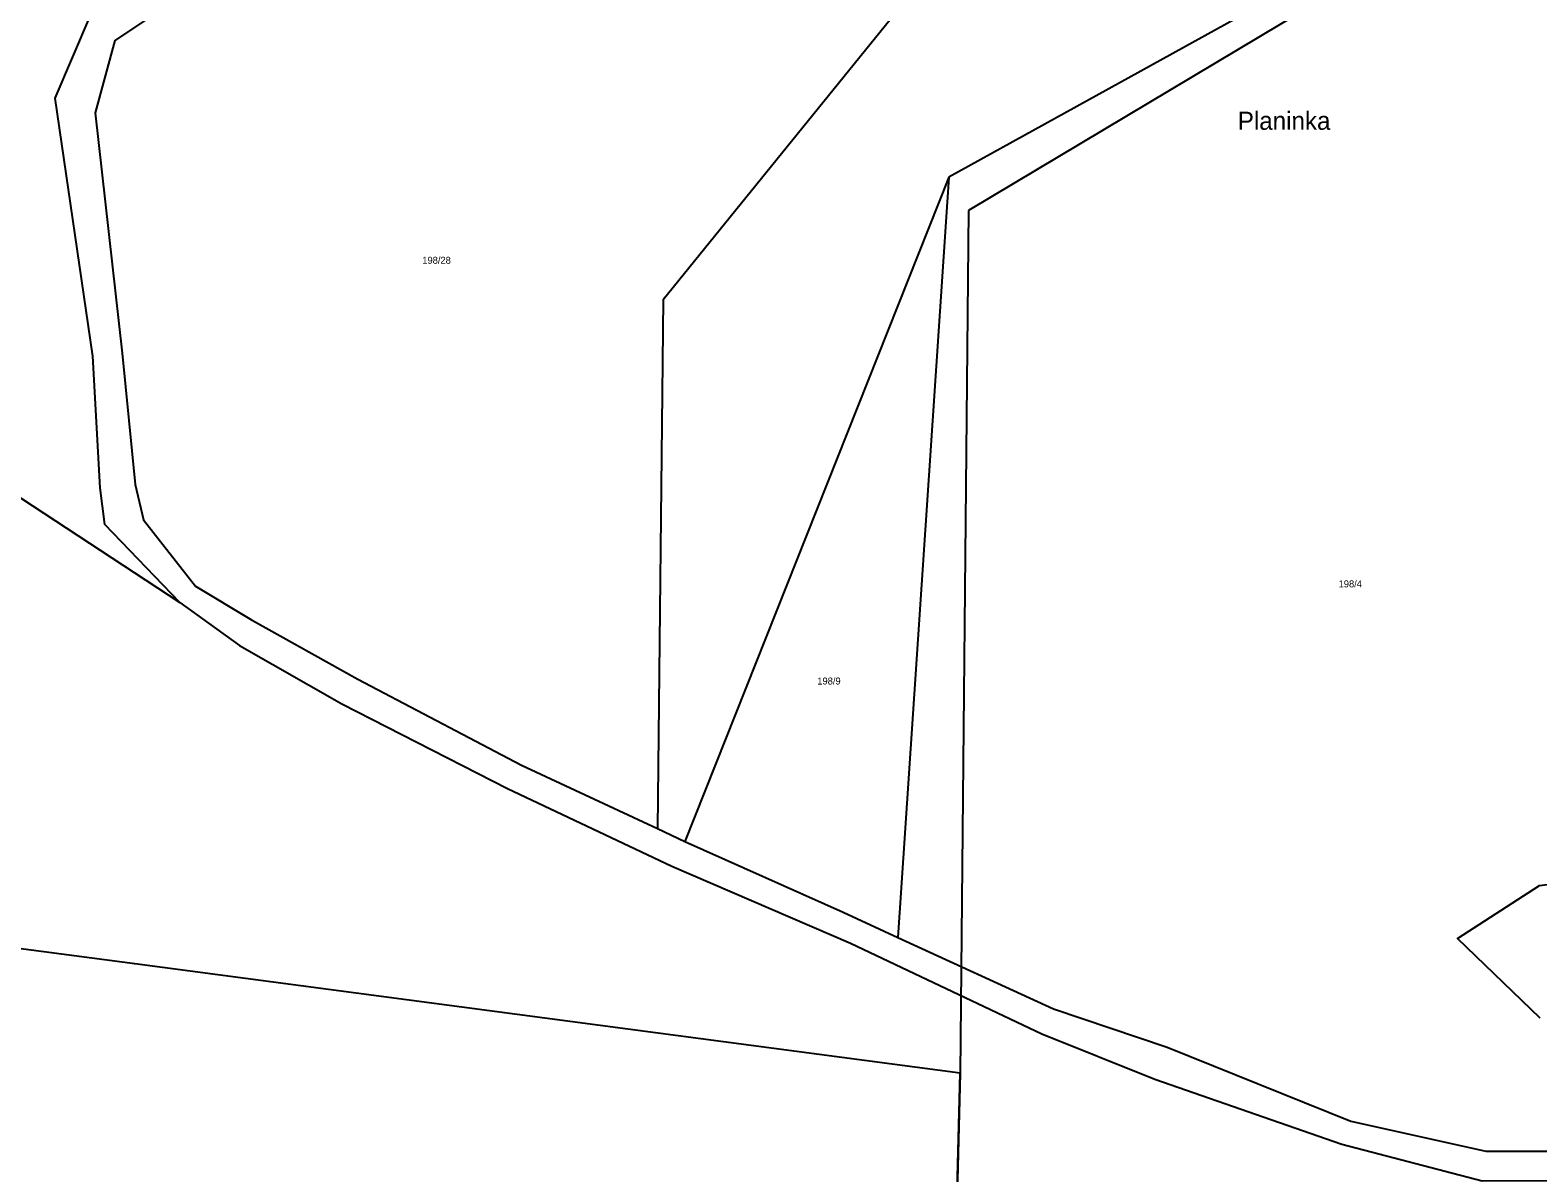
# Model space of a CAD drawing. Extents: x -882150 to -879379, y -1022570 to -1019819.
# Drawn here: x -881044.6 to -880677.3, y -1021005.3 to -1020727.1 of the extents above; entities that cross this region are included whole.
import ezdxf

# ---------------------------------------------------------------- set-up
doc = ezdxf.new("R2010")
doc.units = 0
for name, color, linetype in [('Hranice parcel', 7, 'Continuous'), ('Parcelní čísla', 7, 'Continuous'), ('Pop  PČ popisy', 7, 'Continuous'), ('Vnitřní kresba', 7, 'Continuous')]:
    doc.layers.add(name, color=color, linetype=linetype)

msp = doc.modelspace()

# ---------------------------------------------------------------- linework, layer by layer
at = {"layer": 'Hranice parcel'}
for p, q in [((-880820.82, -1020762.82), (-880885.08, -1020924.59)), ((-880820.82, -1020762.82), (-880833.18, -1020947.96)), ((-881026.34, -1020847.45), (-881027.55, -1020838.52)), ((-881008.12, -1020866.43), (-881026.34, -1020847.45)), ((-880891.74, -1020921.47), (-880885.08, -1020924.59))]:
    msp.add_line(p, q, dxfattribs=at)
for points in [[(-880388.55, -1020572.98), (-880500.39, -1020584.08), (-880515.21, -1020588.29), (-880628.31, -1020656.5), (-880820.82, -1020762.82)], [(-881027.55, -1020838.52), (-881029.32, -1020806.45), (-881038.5, -1020743.58), (-881029.85, -1020723.52), (-881014.17, -1020709.89), (-881009.16, -1020705.54), (-880969.13, -1020690.71), (-880937.29, -1020671.41), (-880868.62, -1020627.96), (-880801.04, -1020578.02)], [(-880933.25, -1020678.46), (-880965.94, -1020699.04), (-881005.01, -1020716.93), (-881023.92, -1020729.61), (-881028.77, -1020747.18), (-881022.14, -1020805.73), (-881018.96, -1020837.69), (-881016.93, -1020846.3), (-881004.27, -1020862.43), (-880990.66, -1020870.64), (-880964.75, -1020885.05), (-880924.85, -1020905.99), (-880891.74, -1020921.47)], [(-880819.89, -1020705.71), (-880890.41, -1020792.7), (-880891.74, -1020921.47)], [(-881136.6, -1020790.54), (-881092.77, -1020818.78), (-881049.52, -1020839.19), (-881008.12, -1020866.43)], [(-880676.73, -1020967.67), (-880696.89, -1020948.24), (-880676.94, -1020935.31), (-880628.16, -1020929), (-880610.75, -1020916.11), (-880604.98, -1020886.94), (-880577.22, -1020878.49), (-880538.33, -1020864.93), (-880517.75, -1020870.05)], [(-881008.12, -1020866.43), (-880993.59, -1020876.88), (-880968.62, -1020891.12), (-880928.33, -1020911.7), (-880888.23, -1020930.64), (-880844.76, -1020949.33), (-880798.1, -1020971.47), (-880770.61, -1020982.51), (-880725.04, -1020998.33), (-880690.89, -1021007.2), (-880644.38, -1021007.09), (-880576.05, -1021016.73)], [(-880765.36, -1021101.69), (-880819, -1021019), (-880818, -1020981), (-880892.25, -1020971.19), (-881019.05, -1020954.44), (-881139.21, -1020938.56), (-881233.47, -1020926.11)], [(-880885.08, -1020924.59), (-880846.54, -1020941.82), (-880833.18, -1020947.96)], [(-880833.18, -1020947.96), (-880795.31, -1020965.36), (-880767.59, -1020974.73), (-880722.86, -1020992.68), (-880690, -1021000), (-880675.05, -1021000)]]:
    msp.add_lwpolyline(points, dxfattribs=at)
at = {"layer": 'Vnitřní kresba'}
for p, q in [((-880508, -1020587), (-880816, -1020771)), ((-880816, -1020771), (-880818, -1020981)), ((-880818, -1020981), (-880819, -1021019))]:
    msp.add_line(p, q, dxfattribs=at)

# ---------------------------------------------------------------- texts
at = {"layer": 'Parcelní čísla'}
for s, p in [('198/28', (-880949.05, -1020783.94)), ('198/4', (-880725.85, -1020862.74)), ('198/9', (-880852.83, -1020886.39))]:
    msp.add_text(s, height=1.7, dxfattribs=at).set_placement(p)
at = {"layer": 'Pop  PČ popisy'}
msp.add_text('Planinka', height=4.4, dxfattribs=at).set_placement((-880750.41, -1020751.32))

doc.saveas('drawing.dxf')
